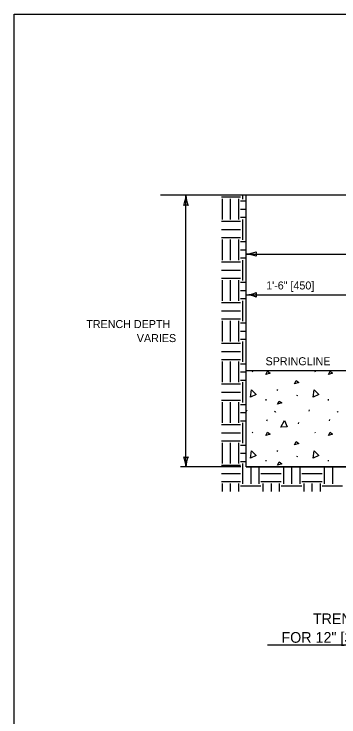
# Model space of a CAD drawing. Extents: x 49991.4 to 50061.4, y 49960.6 to 50011.4.
# Drawn here: x 49999.38 to 50001.82, y 49993.73 to 49999 of the extents above; entities that cross this region are included whole.
import ezdxf

# ---------------------------------------------------------------- set-up
doc = ezdxf.new("R2010")
doc.units = 0
for name, color, linetype in [('Level 1', 7, 'Continuous'), ('Level 2', 7, 'Continuous'), ('Level 3', 7, 'Continuous')]:
    doc.layers.add(name, color=color, linetype=linetype)

msp = doc.modelspace()

# ---------------------------------------------------------------- linework, layer by layer
at = {"layer": 'Level 1'}
for p, q in [((50004.3049, 49997.6424), (50000.4816, 49997.6424)), ((50001.0957, 49997.6424), (50001.0957, 49997.6133)), ((50001.1217, 49995.6066), (50001.1217, 49997.6424)), ((50000.9384, 49997.6297), (50001.0792, 49997.6297)), ((50000.9416, 49997.6144), (50000.9416, 49997.4615)), ((50001.0028, 49997.6144), (50001.0028, 49997.4615)), ((50001.0639, 49997.6144), (50001.0639, 49997.4615)), ((50001.0792, 49997.5991), (50001.1217, 49997.5991)), ((50001.0792, 49997.538), (50001.1217, 49997.538)), ((50000.9384, 49997.4473), (50001.0792, 49997.4473)), ((50001.0792, 49997.4768), (50001.1217, 49997.4768)), ((50001.0957, 49997.4615), (50001.0957, 49997.3086)), ((50000.9384, 49997.3862), (50001.0792, 49997.3862)), ((50000.9384, 49997.325), (50001.0792, 49997.325)), ((50000.9416, 49997.3097), (50000.9416, 49997.1568)), ((50001.0028, 49997.3097), (50001.0028, 49997.1568)), ((50001.0639, 49997.3097), (50001.0639, 49997.1568)), ((50001.0792, 49997.2944), (50001.1217, 49997.2944)), ((50001.0792, 49997.2333), (50001.1217, 49997.2333)), ((50001.0792, 49997.1721), (50001.1217, 49997.1721)), ((50000.9384, 49997.1426), (50001.0792, 49997.1426)), ((50001.0957, 49997.1568), (50001.0957, 49997.004)), ((50000.9384, 49997.0815), (50001.0792, 49997.0815)), ((50000.9384, 49997.0203), (50001.0792, 49997.0203)), ((50000.9416, 49997.005), (50000.9416, 49996.8521)), ((50001.0028, 49997.005), (50001.0028, 49996.8521)), ((50001.0639, 49997.005), (50001.0639, 49996.8521)), ((50001.0792, 49996.9897), (50001.1217, 49996.9897)), ((50001.0792, 49996.9286), (50001.1217, 49996.9286)), ((50001.0792, 49996.8674), (50001.1217, 49996.8674)), ((50001.0957, 49996.8521), (50001.0957, 49996.6993)), ((50000.9384, 49996.8379), (50001.0792, 49996.8379)), ((50000.9384, 49996.7768), (50001.0792, 49996.7768)), ((50000.9384, 49996.7156), (50001.0792, 49996.7156)), ((50000.9416, 49996.7003), (50000.9416, 49996.5474)), ((50001.0028, 49996.7003), (50001.0028, 49996.5474)), ((50001.0639, 49996.7003), (50001.0639, 49996.5474)), ((50001.0792, 49996.685), (50001.1217, 49996.685)), ((50001.0792, 49996.6239), (50001.1217, 49996.6239)), ((50000.9384, 49996.5332), (50001.0792, 49996.5332)), ((50001.0792, 49996.5627), (50001.1217, 49996.5627)), ((50001.0957, 49996.5474), (50001.0957, 49996.3946)), ((50000.9384, 49996.4721), (50001.0792, 49996.4721)), ((50000.9384, 49996.4109), (50001.0792, 49996.4109)), ((50000.9416, 49996.3956), (50000.9416, 49996.2427)), ((50001.0028, 49996.3956), (50001.0028, 49996.2427)), ((50001.0639, 49996.3956), (50001.0639, 49996.2427)), ((50001.0792, 49996.3803), (50001.1217, 49996.3803)), ((50001.1217, 49995.6066), (50001.1217, 49996.3285)), ((50001.1217, 49996.3285), (50001.9464, 49996.3285)), ((50001.1679, 49996.3242), (50001.1718, 49996.3183)), ((50001.6358, 49996.3242), (50001.6397, 49996.3183)), ((50001.0792, 49996.3192), (50001.1217, 49996.3192)), ((50000.9384, 49996.2285), (50001.0792, 49996.2285)), ((50001.0792, 49996.258), (50001.1217, 49996.258)), ((50001.0957, 49996.2427), (50001.0957, 49996.0899)), ((50000.9384, 49996.1674), (50001.0792, 49996.1674)), ((50001.3554, 49996.1786), (50001.3593, 49996.1874)), ((50001.2682, 49996.114), (50001.2692, 49996.1052)), ((50001.5039, 49996.1386), (50001.5078, 49996.1473)), ((50001.7361, 49996.114), (50001.7371, 49996.1052)), ((50000.9384, 49996.1062), (50001.0792, 49996.1062)), ((50000.9416, 49996.0909), (50000.9416, 49995.9381)), ((50001.0028, 49996.0909), (50001.0028, 49995.9381)), ((50001.0639, 49996.0909), (50001.0639, 49995.9381)), ((50001.0792, 49996.0756), (50001.1217, 49996.0756)), ((50001.0792, 49996.0145), (50001.1217, 49996.0145)), ((50001.1249, 49996.0252), (50001.1288, 49996.034)), ((50001.3349, 49996.0252), (50001.3388, 49996.0194)), ((50001.3388, 49996.023), (50001.3427, 49996.0172)), ((50001.5928, 49996.0252), (50001.5967, 49996.034)), ((50001.8028, 49996.0252), (50001.8067, 49996.0194)), ((50001.8067, 49996.023), (50001.8106, 49996.0172)), ((50001.0792, 49995.9533), (50001.1217, 49995.9533)), ((50001.2773, 49995.9528), (50001.2812, 49995.9616)), ((50001.7452, 49995.9528), (50001.7491, 49995.9616)), ((50000.9384, 49995.9238), (50001.0792, 49995.9238)), ((50001.0957, 49995.9381), (50001.0957, 49995.7852)), ((50001.5137, 49995.9304), (50001.5176, 49995.9392)), ((50000.9384, 49995.8627), (50001.0792, 49995.8627)), ((50001.1679, 49995.8679), (50001.1718, 49995.862)), ((50001.6358, 49995.8679), (50001.6397, 49995.862)), ((50000.9384, 49995.8015), (50001.0792, 49995.8015)), ((50000.9416, 49995.7862), (50000.9416, 49995.6334)), ((50001.0028, 49995.7862), (50001.0028, 49995.6334)), ((50001.0639, 49995.7862), (50001.0639, 49995.6334)), ((50001.0792, 49995.771), (50001.1217, 49995.771)), ((50001.0792, 49995.7098), (50001.1217, 49995.7098)), ((50001.3554, 49995.7223), (50001.3593, 49995.7311)), ((50001.5039, 49995.6823), (50001.5078, 49995.6911)), ((50001.0792, 49995.6486), (50001.1217, 49995.6486)), ((50001.2682, 49995.6577), (50001.2692, 49995.6489)), ((50001.7361, 49995.6577), (50001.7371, 49995.6489)), ((50000.9384, 49995.6191), (50001.0792, 49995.6191)), ((50001.0957, 49995.6334), (50001.0957, 49995.4805)), ((50003.6648, 49995.6066), (50001.1217, 49995.6066)), ((50001.1217, 49995.6066), (50003.6648, 49995.6066)), ((50001.1568, 49995.6066), (50001.1568, 49995.4805)), ((50001.218, 49995.6066), (50001.218, 49995.4805)), ((50001.4014, 49995.6066), (50001.4014, 49995.4805)), ((50001.4626, 49995.6066), (50001.4626, 49995.4805)), ((50001.5237, 49995.6066), (50001.5237, 49995.4805)), ((50001.7072, 49995.6066), (50001.7072, 49995.4805)), ((50001.7683, 49995.6066), (50001.7683, 49995.4805)), ((50000.9384, 49995.558), (50001.0792, 49995.558)), ((50001.2321, 49995.558), (50001.385, 49995.558)), ((50001.5379, 49995.558), (50001.6908, 49995.558)), ((50000.9384, 49995.4968), (50001.0792, 49995.4968)), ((50000.9416, 49995.4815), (50000.9416, 49995.4232)), ((50001.0028, 49995.4815), (50001.0028, 49995.4232)), ((50001.0639, 49995.4815), (50001.0639, 49995.4232)), ((50001.2321, 49995.4968), (50001.385, 49995.4968)), ((50001.2474, 49995.4815), (50001.2474, 49995.4232)), ((50001.3086, 49995.4815), (50001.3086, 49995.4232)), ((50001.3697, 49995.4815), (50001.3697, 49995.4232)), ((50001.5379, 49995.4968), (50001.6908, 49995.4968)), ((50001.5532, 49995.4815), (50001.5532, 49995.4232)), ((50001.6143, 49995.4815), (50001.6143, 49995.4232)), ((50001.6755, 49995.4815), (50001.6755, 49995.4232)), ((50001.0792, 49995.4663), (50001.2321, 49995.4663)), ((50001.385, 49995.4663), (50001.5379, 49995.4663)), ((50001.6908, 49995.4663), (50001.8437, 49995.4663))]:
    msp.add_line(p, q, dxfattribs=at)
msp.add_lwpolyline([(49999.3835, 49998.9992), (50016.7501, 49998.9992), (50016.7501, 49987.7988), (49999.3835, 49987.7988)], close=True, dxfattribs=at)
for points in [[(50001.2704, 49996.2988), (50001.2822, 49996.3232), (50001.3017, 49996.3085), (50001.2704, 49996.2988)], [(50001.7383, 49996.2988), (50001.7501, 49996.3232), (50001.7696, 49996.3085), (50001.7383, 49996.2988)], [(50001.4846, 49996.2289), (50001.4963, 49996.2533), (50001.5158, 49996.2387), (50001.4846, 49996.2289)], [(50001.1548, 49996.1284), (50001.1626, 49996.1843), (50001.1976, 49996.1482), (50001.1557, 49996.1288)], [(50001.6227, 49996.1284), (50001.6305, 49996.1843), (50001.6655, 49996.1482), (50001.6237, 49996.1288)], [(50001.3574, 49996.076), (50001.3691, 49996.1005), (50001.3886, 49996.0858), (50001.3574, 49996.076)], [(50001.3818, 49995.904), (50001.4082, 49995.9538), (50001.4287, 49995.9079), (50001.3828, 49995.904)], [(50001.2704, 49995.8425), (50001.2822, 49995.8669), (50001.3017, 49995.8522), (50001.2704, 49995.8425)], [(50001.7383, 49995.8425), (50001.7501, 49995.8669), (50001.7696, 49995.8522), (50001.7383, 49995.8425)], [(50001.4846, 49995.7726), (50001.4963, 49995.7971), (50001.5158, 49995.7824), (50001.4846, 49995.7726)], [(50001.1548, 49995.6722), (50001.1626, 49995.728), (50001.1976, 49995.6919), (50001.1557, 49995.6725)], [(50001.6227, 49995.6722), (50001.6305, 49995.728), (50001.6655, 49995.6919), (50001.6237, 49995.6725)], [(50001.3574, 49995.6197), (50001.3691, 49995.6442), (50001.3886, 49995.6295), (50001.3574, 49995.6197)]]:
    msp.add_lwpolyline(points, dxfattribs=at)
at = {"layer": 'Level 2'}
msp.add_line((50001.283, 49994.2737), (50003.5203, 49994.2737), dxfattribs=at)
at = {"layer": 'Level 3'}
for p, q in [((50000.6711, 49995.6066), (50000.6711, 49997.6424)), ((50001.1217, 49997.2018), (50003.6648, 49997.2018)), ((50001.1217, 49996.8962), (50001.9464, 49996.8962)), ((50001.0817, 49995.6066), (50000.6311, 49995.6066))]:
    msp.add_line(p, q, dxfattribs=at)
for centre, radius, start, end in [((50000.449, 49997.6515), 0.2223, 337.456, 357.6395), ((50000.9038, 49997.6539), 0.233, 182.8273, 202.0772), ((50000.6711, 49997.5141), 0.0548, 72.1388, 107.8612), ((50001.1102, 49997.4346), 0.233, 272.8273, 292.0772), ((50001.2499, 49997.2018), 0.0548, 162.1388, 197.8612), ((50001.1126, 49996.9797), 0.2223, 67.456, 87.6395), ((50001.1102, 49997.1289), 0.233, 272.8273, 292.0772), ((50001.2499, 49996.8962), 0.0548, 162.1388, 197.8612), ((50001.1126, 49996.6741), 0.2223, 67.456, 87.6395), ((50000.6711, 49995.7348), 0.0548, 252.1388, 287.8612), ((50000.4384, 49995.5951), 0.233, 2.8273, 22.0772), ((50000.8932, 49995.5974), 0.2223, 157.456, 177.6395)]:
    msp.add_arc(centre, radius, start, end, dxfattribs=at)

# ---------------------------------------------------------------- texts
at = {"layer": 'Level 2'}
for s, height, p in [('1\'-6" [450]', 0.06, (50001.2719, 49996.9362)), ('TRENCH DEPTH', 0.06, (49999.9249, 49996.647)), ('VARIES', 0.06, (50000.3031, 49996.542)), ('SPRINGLINE', 0.06, (50001.2673, 49996.3685)), ('TRENCH/BEDDING DETAIL', 0.08, (50001.6217, 49994.4297)), ('FOR 12" [300] TO 54" [1350] DIA.', 0.08, (50001.3862, 49994.2897))]:
    msp.add_text(s, height=height, dxfattribs=at).set_placement(p)

doc.saveas('drawing.dxf')
